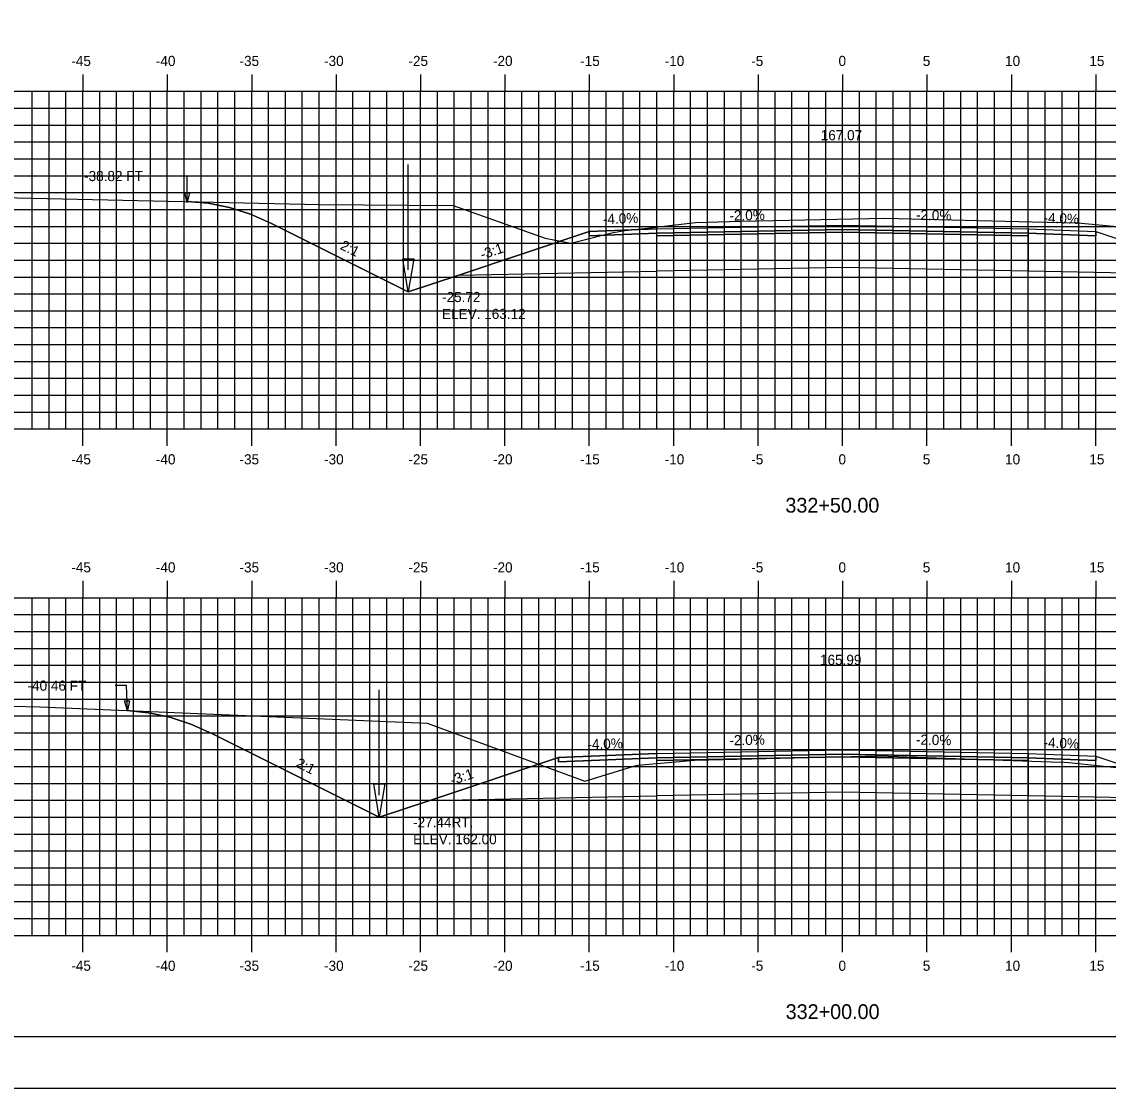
# Model space of a CAD drawing. Extents: x 1141646 to 1141816, y 608981 to 609091.
# Drawn here: x 1141680.4 to 1141744.8, y 608981.3 to 609044.5 of the extents above; entities that cross this region are included whole.
import ezdxf

# ---------------------------------------------------------------- set-up
doc = ezdxf.new("R2010")
doc.units = 0
for name, color, linetype in [('ANNOTATION', 7, 'Continuous'), ('BORDER', 7, 'Continuous'), ('D_Drainage_Ditch_Line', 7, 'Continuous'), ('D_Roadway_Centerline', 7, 'Continuous'), ('D_Roadway_Centerline_Text', 7, 'Continuous'), ('D_Roadway_Edge_Shoulder', 7, 'Continuous'), ('D_Roadway_Edge_TW', 7, 'Continuous'), ('D_Roadway_Pavement', 7, 'Continuous'), ('D_Roadway_SlopeLines', 7, 'Continuous'), ('D_Roadway_SubGrade', 7, 'Continuous'), ('D_Text_Standard', 7, 'Continuous'), ('H_V ANNOTATION', 7, 'Continuous'), ('MAJOR', 7, 'Continuous'), ('MINOR', 7, 'Continuous'), ('PLOT BOUNDARY', 7, 'Continuous'), ('S_Roadway_Centerline', 7, 'Continuous')]:
    doc.layers.add(name, color=color, linetype=linetype)

msp = doc.modelspace()

# ---------------------------------------------------------------- linework, layer by layer
for points in [[(1141690.206, 609033.804), (1141691.456, 609033.702), (1141692.706, 609033.45), (1141693.956, 609033.049), (1141695.206, 609032.498), (1141703.303, 609028.45), (1141706.303, 609029.45), (1141714.026, 609032.025), (1141714.027, 609032.025), (1141718.027, 609032.185), (1141729.027, 609032.405), (1141740.027, 609032.185), (1141744.027, 609032.025), (1141751.751, 609029.45), (1141754.751, 609028.45), (1141761.041, 609031.596), (1141762.291, 609032.145), (1141763.541, 609032.543), (1141764.791, 609032.789), (1141766.041, 609032.884)], [(1141686.671, 609003.648), (1141687.921, 609003.524), (1141689.171, 609003.256), (1141690.421, 609002.846), (1141691.671, 609002.292), (1141701.588, 608997.333), (1141704.588, 608998.333), (1141712.195, 609000.869), (1141712.196, 609000.869), (1141718.027, 609001.102), (1141729.027, 609001.322), (1141740.027, 609001.102), (1141744.027, 609000.942), (1141751.751, 608998.368), (1141754.751, 608997.368), (1141762.545, 609001.265), (1141763.795, 609001.808), (1141765.045, 609002.185), (1141766.295, 609002.397), (1141767.545, 609002.444)]]:
    msp.add_lwpolyline(points)
at = {"layer": 'BORDER'}
msp.add_lwpolyline([(1141654.027, 608984.335), (1141814.027, 608984.335), (1141814.027, 609089.335), (1141654.027, 609089.335)], close=True, dxfattribs=at)
at = {"layer": 'D_Drainage_Ditch_Line'}
for p, q in [((1141703.303, 609029.763), (1141703.303, 609036.006)), ((1141701.588, 608998.646), (1141701.588, 609004.889))]:
    msp.add_line(p, q, dxfattribs=at)
for points in [[(1141702.975, 609030.419), (1141703.631, 609030.419), (1141703.303, 609028.45)], [(1141701.26, 608999.302), (1141701.916, 608999.302), (1141701.588, 608997.333)]]:
    msp.add_lwpolyline(points, close=True, dxfattribs=at)
at = {"layer": 'D_Roadway_Edge_Shoulder'}
for points in [[(1141718.027, 609032.185), (1141714.027, 609032.025), (1141714.027, 609031.775), (1141718.027, 609031.935)], [(1141740.027, 609032.185), (1141744.027, 609032.025), (1141744.027, 609031.775), (1141740.027, 609031.935)], [(1141718.027, 609001.102), (1141712.196, 609000.869), (1141712.196, 609000.619), (1141718.027, 609000.852)], [(1141740.027, 609001.102), (1141744.027, 609000.942), (1141744.027, 609000.692), (1141740.027, 609000.852)]]:
    msp.add_lwpolyline(points, close=True, dxfattribs=at)
at = {"layer": 'D_Roadway_Edge_TW'}
for points in [[(1141718.027, 609031.935), (1141718.027, 609032.185), (1141729.027, 609032.405), (1141740.027, 609032.185), (1141740.027, 609031.935), (1141729.027, 609032.155)], [(1141718.027, 609000.852), (1141718.027, 609001.102), (1141729.027, 609001.322), (1141740.027, 609001.102), (1141740.027, 609000.852), (1141729.027, 609001.072)]]:
    msp.add_lwpolyline(points, close=True, dxfattribs=at)
at = {"layer": 'D_Roadway_Pavement'}
for points in [[(1141718.027, 609031.768), (1141718.027, 609031.935), (1141729.027, 609032.155), (1141740.027, 609031.935), (1141740.027, 609031.768), (1141729.027, 609031.988)], [(1141718.027, 609000.686), (1141718.027, 609000.852), (1141729.027, 609001.072), (1141740.027, 609000.852), (1141740.027, 609000.686), (1141729.027, 609000.906)]]:
    msp.add_lwpolyline(points, close=True, dxfattribs=at)
at = {"layer": 'D_Roadway_SlopeLines'}
for points in [[(1141703.303, 609028.45), (1141695.206, 609032.498), (1141693.956, 609033.049), (1141692.706, 609033.45), (1141691.456, 609033.702), (1141690.206, 609033.804)], [(1141706.303, 609029.45), (1141703.303, 609028.45)], [(1141701.588, 608997.333), (1141691.671, 609002.292), (1141690.421, 609002.846), (1141689.171, 609003.256), (1141687.921, 609003.524), (1141686.671, 609003.648)], [(1141704.588, 608998.333), (1141701.588, 608997.333)]]:
    msp.add_lwpolyline(points, dxfattribs=at)
at = {"layer": 'D_Roadway_SubGrade'}
for points in [[(1141718.027, 609031.768), (1141718.027, 609031.935), (1141714.027, 609031.775), (1141714.027, 609032.025), (1141714.026, 609032.025), (1141706.303, 609029.45), (1141718.027, 609029.685)], [(1141740.027, 609031.768), (1141740.027, 609031.935), (1141744.027, 609031.775), (1141744.027, 609032.025), (1141744.027, 609032.025), (1141751.751, 609029.45), (1141740.027, 609029.685)], [(1141718.027, 609029.685), (1141718.027, 609031.768), (1141729.027, 609031.988), (1141740.027, 609031.768), (1141740.027, 609029.685), (1141729.027, 609029.905)], [(1141718.027, 609000.686), (1141718.027, 609000.852), (1141712.196, 609000.619), (1141712.196, 609000.869), (1141712.195, 609000.869), (1141704.588, 608998.333), (1141718.027, 608998.602)], [(1141718.027, 608998.602), (1141718.027, 609000.686), (1141729.027, 609000.906), (1141740.027, 609000.686), (1141740.027, 608998.602), (1141729.027, 608998.822)], [(1141740.027, 609000.686), (1141740.027, 609000.852), (1141744.027, 609000.692), (1141744.027, 609000.942), (1141744.027, 609000.942), (1141751.751, 608998.368), (1141740.027, 608998.602)]]:
    msp.add_lwpolyline(points, close=True, dxfattribs=at)
at = {"layer": 'D_Text_Standard'}
for points in [[(1141690.206, 609033.748), (1141690.204, 609035.317), (1141689.524, 609035.317)], [(1141686.671, 609003.648), (1141686.618, 609005.127), (1141685.938, 609005.127)]]:
    msp.add_lwpolyline(points, dxfattribs=at)
for points in [[(1141690.206, 609033.748), (1141690.06, 609034.33), (1141690.351, 609034.331)], [(1141686.671, 609003.648), (1141686.504, 609004.225), (1141686.795, 609004.235)]]:
    msp.add_lwpolyline(points, close=True, dxfattribs=at)
at = {"layer": 'MAJOR'}
for p, q in [((1141684.027, 609041.337), (1141684.027, 609040.335)), ((1141689.027, 609041.337), (1141689.027, 609040.335)), ((1141694.027, 609041.337), (1141694.027, 609040.335)), ((1141699.027, 609041.337), (1141699.027, 609040.335)), ((1141704.027, 609041.337), (1141704.027, 609040.335)), ((1141709.027, 609041.337), (1141709.027, 609040.335)), ((1141714.027, 609041.337), (1141714.027, 609040.335)), ((1141719.027, 609041.337), (1141719.027, 609040.335)), ((1141724.027, 609041.337), (1141724.027, 609040.335)), ((1141729.027, 609041.337), (1141729.027, 609040.335)), ((1141734.027, 609041.337), (1141734.027, 609040.335)), ((1141739.027, 609041.337), (1141739.027, 609040.335)), ((1141744.027, 609041.337), (1141744.027, 609040.335)), ((1141659.027, 609040.335), (1141799.027, 609040.335)), ((1141659.027, 609040.335), (1141799.027, 609040.335)), ((1141684.027, 609020.335), (1141684.027, 609040.335)), ((1141689.027, 609020.335), (1141689.027, 609040.335)), ((1141694.027, 609020.335), (1141694.027, 609040.335)), ((1141699.027, 609020.335), (1141699.027, 609040.335)), ((1141704.027, 609020.335), (1141704.027, 609040.335)), ((1141709.027, 609020.335), (1141709.027, 609040.335)), ((1141714.027, 609020.335), (1141714.027, 609040.335)), ((1141719.027, 609020.335), (1141719.027, 609040.335)), ((1141724.027, 609020.335), (1141724.027, 609040.335)), ((1141729.027, 609020.335), (1141729.027, 609040.335)), ((1141734.027, 609020.335), (1141734.027, 609040.335)), ((1141739.027, 609020.335), (1141739.027, 609040.335)), ((1141744.027, 609020.335), (1141744.027, 609040.335)), ((1141659.027, 609035.335), (1141799.027, 609035.335)), ((1141659.027, 609030.335), (1141799.027, 609030.335)), ((1141659.027, 609025.335), (1141799.027, 609025.335)), ((1141659.027, 609020.335), (1141799.027, 609020.335)), ((1141659.027, 609020.335), (1141799.027, 609020.335)), ((1141684.027, 609019.333), (1141684.027, 609020.335)), ((1141689.027, 609019.333), (1141689.027, 609020.335)), ((1141694.027, 609019.333), (1141694.027, 609020.335)), ((1141699.027, 609019.333), (1141699.027, 609020.335)), ((1141704.027, 609019.333), (1141704.027, 609020.335)), ((1141709.027, 609019.333), (1141709.027, 609020.335)), ((1141714.027, 609019.333), (1141714.027, 609020.335)), ((1141719.027, 609019.333), (1141719.027, 609020.335)), ((1141724.027, 609019.333), (1141724.027, 609020.335)), ((1141729.027, 609019.333), (1141729.027, 609020.335)), ((1141734.027, 609019.333), (1141734.027, 609020.335)), ((1141739.027, 609019.333), (1141739.027, 609020.335)), ((1141744.027, 609019.333), (1141744.027, 609020.335)), ((1141684.027, 609011.337), (1141684.027, 609010.335)), ((1141689.027, 609011.337), (1141689.027, 609010.335)), ((1141694.027, 609011.337), (1141694.027, 609010.335)), ((1141699.027, 609011.337), (1141699.027, 609010.335)), ((1141704.027, 609011.337), (1141704.027, 609010.335)), ((1141709.027, 609011.337), (1141709.027, 609010.335)), ((1141714.027, 609011.337), (1141714.027, 609010.335)), ((1141719.027, 609011.337), (1141719.027, 609010.335)), ((1141724.027, 609011.337), (1141724.027, 609010.335)), ((1141729.027, 609011.337), (1141729.027, 609010.335)), ((1141734.027, 609011.337), (1141734.027, 609010.335)), ((1141739.027, 609011.337), (1141739.027, 609010.335)), ((1141744.027, 609011.337), (1141744.027, 609010.335)), ((1141659.027, 609010.335), (1141799.027, 609010.335)), ((1141659.027, 609010.335), (1141799.027, 609010.335)), ((1141684.027, 608990.335), (1141684.027, 609010.335)), ((1141689.027, 608990.335), (1141689.027, 609010.335)), ((1141694.027, 608990.335), (1141694.027, 609010.335)), ((1141699.027, 608990.335), (1141699.027, 609010.335)), ((1141704.027, 608990.335), (1141704.027, 609010.335)), ((1141709.027, 608990.335), (1141709.027, 609010.335)), ((1141714.027, 608990.335), (1141714.027, 609010.335)), ((1141719.027, 608990.335), (1141719.027, 609010.335)), ((1141724.027, 608990.335), (1141724.027, 609010.335)), ((1141729.027, 608990.335), (1141729.027, 609010.335)), ((1141734.027, 608990.335), (1141734.027, 609010.335)), ((1141739.027, 608990.335), (1141739.027, 609010.335)), ((1141744.027, 608990.335), (1141744.027, 609010.335)), ((1141659.027, 609005.335), (1141799.027, 609005.335)), ((1141659.027, 609000.335), (1141799.027, 609000.335)), ((1141659.027, 608995.335), (1141799.027, 608995.335)), ((1141659.027, 608990.335), (1141799.027, 608990.335)), ((1141659.027, 608990.335), (1141799.027, 608990.335)), ((1141684.027, 608989.333), (1141684.027, 608990.335)), ((1141689.027, 608989.333), (1141689.027, 608990.335)), ((1141694.027, 608989.333), (1141694.027, 608990.335)), ((1141699.027, 608989.333), (1141699.027, 608990.335)), ((1141704.027, 608989.333), (1141704.027, 608990.335)), ((1141709.027, 608989.333), (1141709.027, 608990.335)), ((1141714.027, 608989.333), (1141714.027, 608990.335)), ((1141719.027, 608989.333), (1141719.027, 608990.335)), ((1141724.027, 608989.333), (1141724.027, 608990.335)), ((1141729.027, 608989.333), (1141729.027, 608990.335)), ((1141734.027, 608989.333), (1141734.027, 608990.335)), ((1141739.027, 608989.333), (1141739.027, 608990.335)), ((1141744.027, 608989.333), (1141744.027, 608990.335))]:
    msp.add_line(p, q, dxfattribs=at)
at = {"layer": 'MINOR'}
for p, q in [((1141681.027, 609020.335), (1141681.027, 609040.335)), ((1141682.027, 609020.335), (1141682.027, 609040.335)), ((1141683.027, 609020.335), (1141683.027, 609040.335)), ((1141685.027, 609020.335), (1141685.027, 609040.335)), ((1141686.027, 609020.335), (1141686.027, 609040.335)), ((1141687.027, 609020.335), (1141687.027, 609040.335)), ((1141688.027, 609020.335), (1141688.027, 609040.335)), ((1141690.027, 609020.335), (1141690.027, 609040.335)), ((1141691.027, 609020.335), (1141691.027, 609040.335)), ((1141692.027, 609020.335), (1141692.027, 609040.335)), ((1141693.027, 609020.335), (1141693.027, 609040.335)), ((1141695.027, 609020.335), (1141695.027, 609040.335)), ((1141696.027, 609020.335), (1141696.027, 609040.335)), ((1141697.027, 609020.335), (1141697.027, 609040.335)), ((1141698.027, 609020.335), (1141698.027, 609040.335)), ((1141700.027, 609020.335), (1141700.027, 609040.335)), ((1141701.027, 609020.335), (1141701.027, 609040.335)), ((1141702.027, 609020.335), (1141702.027, 609040.335)), ((1141703.027, 609020.335), (1141703.027, 609040.335)), ((1141705.027, 609020.335), (1141705.027, 609040.335)), ((1141706.027, 609020.335), (1141706.027, 609040.335)), ((1141707.027, 609020.335), (1141707.027, 609040.335)), ((1141708.027, 609020.335), (1141708.027, 609040.335)), ((1141710.027, 609020.335), (1141710.027, 609040.335)), ((1141711.027, 609020.335), (1141711.027, 609040.335)), ((1141712.027, 609020.335), (1141712.027, 609040.335)), ((1141713.027, 609020.335), (1141713.027, 609040.335)), ((1141715.027, 609020.335), (1141715.027, 609040.335)), ((1141716.027, 609020.335), (1141716.027, 609040.335)), ((1141717.027, 609020.335), (1141717.027, 609040.335)), ((1141718.027, 609020.335), (1141718.027, 609040.335)), ((1141720.027, 609020.335), (1141720.027, 609040.335)), ((1141721.027, 609020.335), (1141721.027, 609040.335)), ((1141722.027, 609020.335), (1141722.027, 609040.335)), ((1141723.027, 609020.335), (1141723.027, 609040.335)), ((1141725.027, 609020.335), (1141725.027, 609040.335)), ((1141726.027, 609020.335), (1141726.027, 609040.335)), ((1141727.027, 609020.335), (1141727.027, 609040.335)), ((1141728.027, 609020.335), (1141728.027, 609040.335)), ((1141730.027, 609020.335), (1141730.027, 609040.335)), ((1141731.027, 609020.335), (1141731.027, 609040.335)), ((1141732.027, 609020.335), (1141732.027, 609040.335)), ((1141733.027, 609020.335), (1141733.027, 609040.335)), ((1141735.027, 609020.335), (1141735.027, 609040.335)), ((1141736.027, 609020.335), (1141736.027, 609040.335)), ((1141737.027, 609020.335), (1141737.027, 609040.335)), ((1141738.027, 609020.335), (1141738.027, 609040.335)), ((1141740.027, 609020.335), (1141740.027, 609040.335)), ((1141741.027, 609020.335), (1141741.027, 609040.335)), ((1141742.027, 609020.335), (1141742.027, 609040.335)), ((1141743.027, 609020.335), (1141743.027, 609040.335)), ((1141659.027, 609039.335), (1141799.027, 609039.335)), ((1141659.027, 609038.335), (1141799.027, 609038.335)), ((1141659.027, 609037.335), (1141799.027, 609037.335)), ((1141659.027, 609036.335), (1141799.027, 609036.335)), ((1141659.027, 609034.335), (1141799.027, 609034.335)), ((1141659.027, 609033.335), (1141799.027, 609033.335)), ((1141659.027, 609032.335), (1141799.027, 609032.335)), ((1141659.027, 609031.335), (1141799.027, 609031.335)), ((1141659.027, 609029.335), (1141799.027, 609029.335)), ((1141659.027, 609028.335), (1141799.027, 609028.335)), ((1141659.027, 609027.335), (1141799.027, 609027.335)), ((1141659.027, 609026.335), (1141799.027, 609026.335)), ((1141659.027, 609024.335), (1141799.027, 609024.335)), ((1141659.027, 609023.335), (1141799.027, 609023.335)), ((1141659.027, 609022.335), (1141799.027, 609022.335)), ((1141659.027, 609021.335), (1141799.027, 609021.335)), ((1141681.027, 608990.335), (1141681.027, 609010.335)), ((1141682.027, 608990.335), (1141682.027, 609010.335)), ((1141683.027, 608990.335), (1141683.027, 609010.335)), ((1141685.027, 608990.335), (1141685.027, 609010.335)), ((1141686.027, 608990.335), (1141686.027, 609010.335)), ((1141687.027, 608990.335), (1141687.027, 609010.335)), ((1141688.027, 608990.335), (1141688.027, 609010.335)), ((1141690.027, 608990.335), (1141690.027, 609010.335)), ((1141691.027, 608990.335), (1141691.027, 609010.335)), ((1141692.027, 608990.335), (1141692.027, 609010.335)), ((1141693.027, 608990.335), (1141693.027, 609010.335)), ((1141695.027, 608990.335), (1141695.027, 609010.335)), ((1141696.027, 608990.335), (1141696.027, 609010.335)), ((1141697.027, 608990.335), (1141697.027, 609010.335)), ((1141698.027, 608990.335), (1141698.027, 609010.335)), ((1141700.027, 608990.335), (1141700.027, 609010.335)), ((1141701.027, 608990.335), (1141701.027, 609010.335)), ((1141702.027, 608990.335), (1141702.027, 609010.335)), ((1141703.027, 608990.335), (1141703.027, 609010.335)), ((1141705.027, 608990.335), (1141705.027, 609010.335)), ((1141706.027, 608990.335), (1141706.027, 609010.335)), ((1141707.027, 608990.335), (1141707.027, 609010.335)), ((1141708.027, 608990.335), (1141708.027, 609010.335)), ((1141710.027, 608990.335), (1141710.027, 609010.335)), ((1141711.027, 608990.335), (1141711.027, 609010.335)), ((1141712.027, 608990.335), (1141712.027, 609010.335)), ((1141713.027, 608990.335), (1141713.027, 609010.335)), ((1141715.027, 608990.335), (1141715.027, 609010.335)), ((1141716.027, 608990.335), (1141716.027, 609010.335)), ((1141717.027, 608990.335), (1141717.027, 609010.335)), ((1141718.027, 608990.335), (1141718.027, 609010.335)), ((1141720.027, 608990.335), (1141720.027, 609010.335)), ((1141721.027, 608990.335), (1141721.027, 609010.335)), ((1141722.027, 608990.335), (1141722.027, 609010.335)), ((1141723.027, 608990.335), (1141723.027, 609010.335)), ((1141725.027, 608990.335), (1141725.027, 609010.335)), ((1141726.027, 608990.335), (1141726.027, 609010.335)), ((1141727.027, 608990.335), (1141727.027, 609010.335)), ((1141728.027, 608990.335), (1141728.027, 609010.335)), ((1141730.027, 608990.335), (1141730.027, 609010.335)), ((1141731.027, 608990.335), (1141731.027, 609010.335)), ((1141732.027, 608990.335), (1141732.027, 609010.335)), ((1141733.027, 608990.335), (1141733.027, 609010.335)), ((1141735.027, 608990.335), (1141735.027, 609010.335)), ((1141736.027, 608990.335), (1141736.027, 609010.335)), ((1141737.027, 608990.335), (1141737.027, 609010.335)), ((1141738.027, 608990.335), (1141738.027, 609010.335)), ((1141740.027, 608990.335), (1141740.027, 609010.335)), ((1141741.027, 608990.335), (1141741.027, 609010.335)), ((1141742.027, 608990.335), (1141742.027, 609010.335)), ((1141743.027, 608990.335), (1141743.027, 609010.335)), ((1141659.027, 609009.335), (1141799.027, 609009.335)), ((1141659.027, 609008.335), (1141799.027, 609008.335)), ((1141659.027, 609007.335), (1141799.027, 609007.335)), ((1141659.027, 609006.335), (1141799.027, 609006.335)), ((1141659.027, 609004.335), (1141799.027, 609004.335)), ((1141659.027, 609003.335), (1141799.027, 609003.335)), ((1141659.027, 609002.335), (1141799.027, 609002.335)), ((1141659.027, 609001.335), (1141799.027, 609001.335)), ((1141659.027, 608999.335), (1141799.027, 608999.335)), ((1141659.027, 608998.335), (1141799.027, 608998.335)), ((1141659.027, 608997.335), (1141799.027, 608997.335)), ((1141659.027, 608996.335), (1141799.027, 608996.335)), ((1141659.027, 608994.335), (1141799.027, 608994.335)), ((1141659.027, 608993.335), (1141799.027, 608993.335)), ((1141659.027, 608992.335), (1141799.027, 608992.335)), ((1141659.027, 608991.335), (1141799.027, 608991.335))]:
    msp.add_line(p, q, dxfattribs=at)
at = {"layer": 'PLOT BOUNDARY'}
msp.add_lwpolyline([(1141645.934, 608981.276), (1141815.934, 608981.276), (1141815.934, 609091.276), (1141645.934, 609091.276)], close=True, dxfattribs=at)
at = {"layer": 'S_Roadway_Centerline'}
for points in [[(1141678.167, 609033.767), (1141679.234, 609034.048), (1141698.041, 609033.63), (1141705.97, 609033.574), (1141711.406, 609031.629), (1141712.938, 609031.34), (1141715.436, 609031.97), (1141716.134, 609032.093), (1141717.099, 609032.186), (1141720.325, 609032.555), (1141723.008, 609032.647), (1141731.533, 609032.829), (1141740.258, 609032.604), (1141742.967, 609032.542), (1141745.916, 609032.271), (1141747.023, 609032.157), (1141748.557, 609031.535), (1141749.326, 609031.358), (1141752.88, 609032.733), (1141753.796, 609033.073), (1141762.777, 609032.834), (1141777.873, 609033.068)], [(1141676.132, 609003.905), (1141676.422, 609003.981), (1141681.475, 609003.868), (1141704.424, 609002.897), (1141713.381, 608999.604), (1141713.764, 608999.466), (1141716.715, 609000.383), (1141716.794, 609000.403), (1141716.895, 609000.414), (1141720.259, 609000.712), (1141730.384, 609000.959), (1141731.148, 609000.975), (1141741.378, 609000.622), (1141742.175, 609000.6), (1141742.437, 609000.576), (1141745.801, 609000.225), (1141745.956, 609000.162), (1141747.669, 608999.515), (1141754.519, 609002.541), (1141754.929, 609002.699), (1141757.261, 609002.735), (1141777.166, 609002.172)]]:
    msp.add_lwpolyline(points, dxfattribs=at)

# ---------------------------------------------------------------- texts
at = {"layer": 'ANNOTATION'}
for s, rotation, p in [('-2.0%', 1.14576, (1141722.33, 609032.671)), ('-2.0%', 358.85424, (1141733.37, 609032.718)), ('-4.0%', 2.29061, (1141714.843, 609032.458)), ('-4.0%', 357.70939, (1141740.923, 609032.55)), ('2:1', 333.43495, (1141699.222, 609031.009)), ('-3:1', 18.43482, (1141707.682, 609030.364)), ('-4.0%', 2.29061, (1141713.927, 609001.339)), ('-2.0%', 1.14576, (1141722.33, 609001.589)), ('-2.0%', 358.85424, (1141733.37, 609001.636)), ('-4.0%', 357.70939, (1141740.923, 609001.467)), ('2:1', 333.43495, (1141696.596, 609000.347)), ('-3:1', 18.43483, (1141705.909, 608999.228))]:
    msp.add_text(s, height=0.6, rotation=rotation, dxfattribs=at).set_placement(p)
at = {"layer": 'D_Roadway_Centerline'}
for s, p in [('C', (1141729.022, 609032.405)), ('L', (1141729.027, 609032.398)), ('C', (1141729.022, 609001.322)), ('C', (1141729.022, 609001.322)), ('L', (1141729.027, 609001.315)), ('L', (1141729.027, 609001.315))]:
    msp.add_text(s, height=0.0146, dxfattribs=at).set_placement(p)
at = {"layer": 'D_Roadway_Centerline_Text'}
for s, p in [('167.07', (1141727.732, 609037.437)), ('165.99', (1141727.69, 609006.354))]:
    msp.add_text(s, height=0.6, dxfattribs=at).set_placement(p)
at = {"layer": 'D_Text_Standard'}
for s, p in [('-38.82 FT', (1141684.101, 609035.017)), ('-25.72', (1141705.303, 609027.85)), ('ELEV. 163.12', (1141705.303, 609026.848)), ('-40.46 FT', (1141680.751, 609004.827)), ('-27.44RT.', (1141703.588, 608996.733)), ('ELEV. 162.00', (1141703.588, 608995.731))]:
    msp.add_text(s, height=0.6, dxfattribs=at).set_placement(p)
at = {"layer": 'H_V ANNOTATION'}
for s, height, p in [('-45', 0.6, (1141683.345, 609041.835)), ('-40', 0.6, (1141688.353, 609041.835)), ('-35', 0.6, (1141693.307, 609041.835)), ('-30', 0.6, (1141698.315, 609041.835)), ('-25', 0.6, (1141703.313, 609041.835)), ('-20', 0.6, (1141708.321, 609041.835)), ('-15', 0.6, (1141713.484, 609041.835)), ('-10', 0.6, (1141718.492, 609041.835)), ('-5', 0.6, (1141723.618, 609041.835)), ('0', 0.6, (1141728.786, 609041.835)), ('5', 0.6, (1141733.778, 609041.835)), ('10', 0.6, (1141738.653, 609041.835)), ('15', 0.6, (1141743.645, 609041.835)), ('-45', 0.6, (1141683.345, 609018.235)), ('-40', 0.6, (1141688.353, 609018.235)), ('-35', 0.6, (1141693.307, 609018.235)), ('-30', 0.6, (1141698.315, 609018.235)), ('-25', 0.6, (1141703.313, 609018.235)), ('-20', 0.6, (1141708.321, 609018.235)), ('-15', 0.6, (1141713.484, 609018.235)), ('-10', 0.6, (1141718.492, 609018.235)), ('-5', 0.6, (1141723.618, 609018.235)), ('0', 0.6, (1141728.786, 609018.235)), ('5', 0.6, (1141733.778, 609018.235)), ('10', 0.6, (1141738.653, 609018.235)), ('15', 0.6, (1141743.645, 609018.235)), ('332+50.00', 0.875, (1141725.641, 609015.378)), ('-45', 0.6, (1141683.345, 609011.835)), ('-40', 0.6, (1141688.353, 609011.835)), ('-35', 0.6, (1141693.307, 609011.835)), ('-30', 0.6, (1141698.315, 609011.835)), ('-25', 0.6, (1141703.313, 609011.835)), ('-20', 0.6, (1141708.321, 609011.835)), ('-15', 0.6, (1141713.484, 609011.835)), ('-10', 0.6, (1141718.492, 609011.835)), ('-5', 0.6, (1141723.618, 609011.835)), ('0', 0.6, (1141728.786, 609011.835)), ('5', 0.6, (1141733.778, 609011.835)), ('10', 0.6, (1141738.653, 609011.835)), ('15', 0.6, (1141743.645, 609011.835)), ('-45', 0.6, (1141683.345, 608988.235)), ('-40', 0.6, (1141688.353, 608988.235)), ('-35', 0.6, (1141693.307, 608988.235)), ('-30', 0.6, (1141698.315, 608988.235)), ('-25', 0.6, (1141703.313, 608988.235)), ('-20', 0.6, (1141708.321, 608988.235)), ('-15', 0.6, (1141713.484, 608988.235)), ('-10', 0.6, (1141718.492, 608988.235)), ('-5', 0.6, (1141723.618, 608988.235)), ('0', 0.6, (1141728.786, 608988.235)), ('5', 0.6, (1141733.778, 608988.235)), ('10', 0.6, (1141738.653, 608988.235)), ('15', 0.6, (1141743.645, 608988.235)), ('332+00.00', 0.875, (1141725.656, 608985.378))]:
    msp.add_text(s, height=height, dxfattribs=at).set_placement(p)
at = {"layer": 'S_Roadway_Centerline'}
for s, p in [('C', (1141731.528, 609032.829)), ('L', (1141731.533, 609032.822)), ('C', (1141731.143, 609000.975)), ('L', (1141731.148, 609000.968))]:
    msp.add_text(s, height=0.0146, dxfattribs=at).set_placement(p)

doc.saveas('drawing.dxf')
